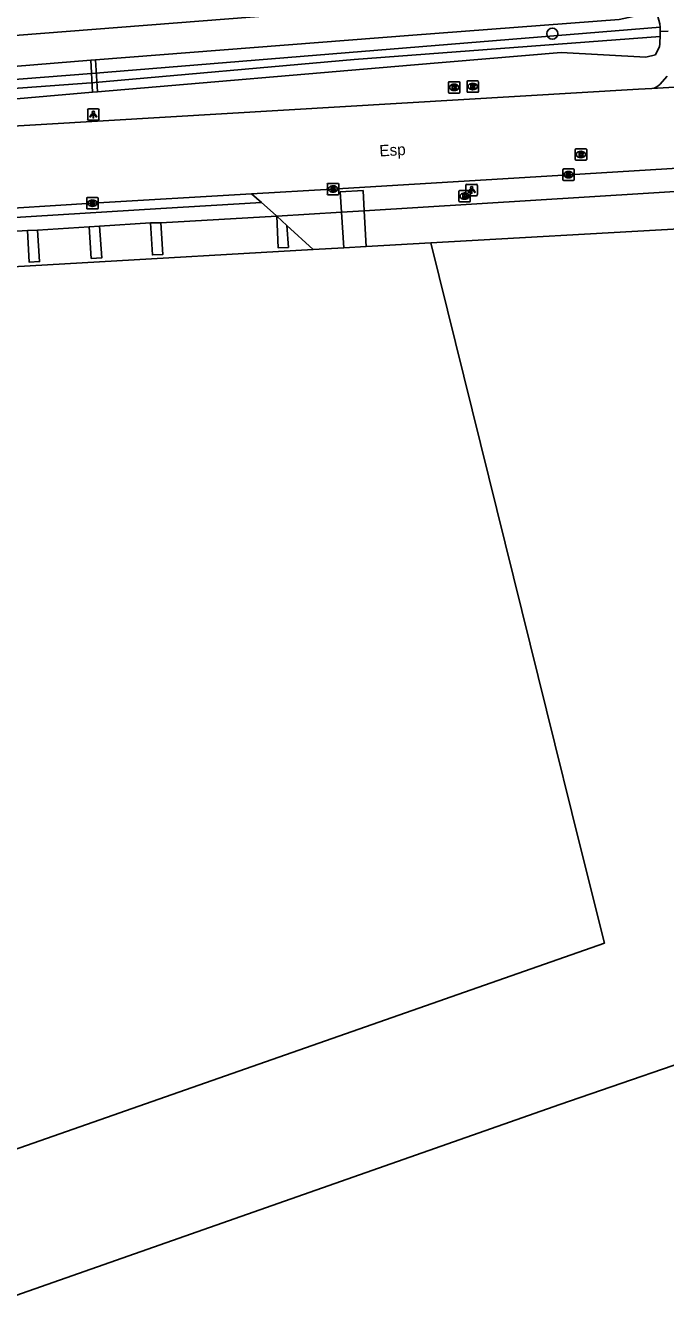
# Model space of a CAD drawing. Extents: x 161389 to 162585, y 388479 to 389761.
# Drawn here: x 162034.7 to 162090.8, y 388865.1 to 388977.1 of the extents above; entities that cross this region are included whole.
import ezdxf

# ---------------------------------------------------------------- set-up
doc = ezdxf.new("R2010")
doc.units = 0
for name, color, linetype in [('IMGEO_Berm_groen', 7, 'Continuous'), ('IMGEO_Boom', 7, 'Continuous'), ('IMGEO_Brandkraan', 7, 'Continuous'), ('IMGEO_Dek', 7, 'Continuous'), ('IMGEO_Grasland_overig', 7, 'Continuous'), ('IMGEO_Groenvoorziening', 7, 'Continuous'), ('IMGEO_Kolk', 7, 'Continuous'), ('IMGEO_Lichtpunt', 7, 'Continuous'), ('IMGEO_Openbare_ruimte_label', 7, 'Continuous'), ('IMGEO_Pand', 7, 'Continuous'), ('IMGEO_Rijbaan_lokaal_gesloten', 7, 'Continuous'), ('IMGEO_Rijbaan_lokaal_open', 7, 'Continuous'), ('IMGEO_Rioolput', 7, 'Continuous'), ('IMGEO_Voetpad_gesloten', 7, 'Continuous'), ('IMGEO_Voetpad_open', 7, 'Continuous'), ('IMGEO_Waterloop', 7, 'Continuous')]:
    doc.layers.add(name, color=color, linetype=linetype)

msp = doc.modelspace()

# ---------------------------------------------------------------- linework, layer by layer
at = {"layer": 'IMGEO_Berm_groen'}
for points in [[(162090.32, 388976.08), (162090.3, 388975.58), (162090.29, 388975.42), (162090.26, 388975.21), (162089.92, 388974.48), (162089.09, 388974.29), (162081.65, 388974.7), (162068.44, 388973.58), (162041, 388971.25), (162040.56, 388971.22), (161994.51, 388967.19), (161960.26, 388964.84), (161958.25, 388964.73)], [(162091.02, 388976.56), (162090.33, 388976.53)]]:
    msp.add_lwpolyline(points, dxfattribs=at)
at = {"layer": 'IMGEO_Boom'}
msp.add_circle((162080.88, 388976.34), 0.489, dxfattribs=at)
at = {"layer": 'IMGEO_Brandkraan'}
for p, q in [((162072.69, 388961.67), (162072.69, 388962.53)), ((162072.77, 388962.6), (162073.62, 388962.6)), ((162073.18, 388962.38), (162073.21, 388962.38)), ((162073.69, 388962.53), (162073.69, 388961.67)), ((162073.62, 388961.6), (162072.77, 388961.6)), ((162073.2, 388961.82), (162073.18, 388961.82))]:
    msp.add_line(p, q, dxfattribs=at)
for points in [[(162072.69, 388961.67), (162072.69, 388962.53)], [(162072.77, 388962.6), (162073.62, 388962.6)], [(162073.04, 388962.3), (162073.04, 388961.9), (162073.25, 388961.9)], [(162073.27, 388962.3), (162073.04, 388962.3)], [(162073.22, 388962.22), (162073.17, 388962.22), (162073.17, 388962.14)], [(162073.69, 388962.53), (162073.69, 388961.67)], [(162073.62, 388961.6), (162072.77, 388961.6)], [(162073.17, 388962.14), (162073.22, 388962.14)], [(162073.23, 388962.07), (162073.17, 388962.07), (162073.17, 388961.98)], [(162073.17, 388961.98), (162073.23, 388961.98)]]:
    msp.add_lwpolyline(points, dxfattribs=at)
for centre, radius, start, end in [((162072.77, 388962.52), 0.0765, 91.552, 178.448), ((162072.77, 388962.52), 0.0765, 91.552, 178.448), ((162073.22, 388962.18), 0.0379, 267.8285, 90.9355), ((162073.28, 388962.15), 0.145, 59.4692, 91.5367), ((162073.3, 388962.2), 0.0922, 285.5137, 58.1501), ((162073.62, 388962.52), 0.0765, 1.552, 88.448), ((162073.62, 388962.52), 0.0765, 1.552, 88.448), ((162072.77, 388961.67), 0.0765, 181.552, 268.448), ((162072.77, 388961.67), 0.0765, 181.552, 268.448), ((162073.23, 388962.03), 0.0404, 269.8759, 90.5077), ((162073.26, 388962.15), 0.251, 268.6676, 293.5347), ((162073.31, 388962.01), 0.105, 301.3115, 78.989), ((162073.62, 388961.67), 0.0765, 271.552, 358.448), ((162073.62, 388961.67), 0.0765, 271.552, 358.448)]:
    msp.add_arc(centre, radius, start, end, dxfattribs=at)
for centre, major_axis, ratio, start_param, end_param in [((162073.18, 388962.1), (-0.387, 0.002), 0.722429, 4.712389, 7.853982), ((162073.2, 388962.1), (-0.39, 0.002), 0.717154, 1.570796, 4.712389)]:
    msp.add_ellipse(centre, major_axis=major_axis, ratio=ratio, start_param=start_param, end_param=end_param, dxfattribs=at)
at = {"layer": 'IMGEO_Dek'}
msp.add_lwpolyline([(162040.84, 388974.05), (162040.43, 388974.02), (162040.56, 388971.22), (162041, 388971.25)], close=True, dxfattribs=at)
at = {"layer": 'IMGEO_Grasland_overig'}
msp.add_lwpolyline([(161937.26, 388968.67), (162000, 388973.56), (162090.78, 388980.64)], dxfattribs=at)
at = {"layer": 'IMGEO_Groenvoorziening'}
msp.add_lwpolyline([(162090.32, 388976.9), (162090.31, 388977.2), (162090.14, 388977.85), (162089.45, 388978.17), (162086.74, 388977.59), (162068.65, 388976.22), (162040.84, 388974.05), (162040.43, 388974.02), (162015.77, 388972.01), (161959.76, 388967.69), (161957.89, 388967.38), (161957.63, 388966.99), (161957.64, 388966.8)], dxfattribs=at)
at = {"layer": 'IMGEO_Kolk'}
for p, q in [((162081.8, 388963.55), (162081.8, 388964.4)), ((162081.87, 388964.48), (162082.73, 388964.48)), ((162082.8, 388964.4), (162082.8, 388963.55)), ((162082.73, 388963.48), (162081.87, 388963.48)), ((162082.29, 388964.26), (162082.31, 388964.26)), ((162082.31, 388963.7), (162082.29, 388963.7)), ((162061.16, 388962.29), (162061.16, 388963.15)), ((162061.23, 388963.22), (162062.08, 388963.22)), ((162062.08, 388962.22), (162061.23, 388962.22)), ((162061.64, 388963), (162061.67, 388963)), ((162061.67, 388962.44), (162061.64, 388962.44)), ((162062.16, 388963.15), (162062.16, 388962.29)), ((162040.07, 388961.05), (162040.07, 388961.9)), ((162040.14, 388961.98), (162040.99, 388961.98)), ((162040.58, 388961.2), (162040.55, 388961.2)), ((162040.56, 388961.76), (162040.58, 388961.76)), ((162041.07, 388961.9), (162041.07, 388961.05)), ((162040.99, 388960.98), (162040.14, 388960.98))]:
    msp.add_line(p, q, dxfattribs=at)
for points in [[(162081.8, 388963.55), (162081.8, 388964.4)], [(162081.87, 388964.48), (162082.73, 388964.48)], [(162082.8, 388964.4), (162082.8, 388963.55)], [(162082.73, 388963.48), (162081.87, 388963.48)], [(162082.12, 388964.18), (162082.24, 388964.18), (162082.24, 388964.03), (162082.37, 388964.18), (162082.54, 388964.18), (162082.39, 388964.03), (162082.54, 388963.78), (162082.39, 388963.78), (162082.31, 388963.94), (162082.24, 388963.87), (162082.24, 388963.78), (162082.12, 388963.78), (162082.12, 388964.18)], [(162061.16, 388962.29), (162061.16, 388963.15)], [(162061.23, 388963.22), (162062.08, 388963.22)], [(162062.08, 388962.22), (162061.23, 388962.22)], [(162061.48, 388962.92), (162061.6, 388962.92), (162061.6, 388962.77), (162061.73, 388962.92), (162061.89, 388962.92), (162061.75, 388962.77), (162061.9, 388962.52), (162061.75, 388962.52), (162061.66, 388962.68), (162061.6, 388962.62), (162061.6, 388962.52), (162061.48, 388962.52), (162061.48, 388962.92)], [(162062.16, 388963.15), (162062.16, 388962.29)], [(162040.07, 388961.05), (162040.07, 388961.9)], [(162040.14, 388961.98), (162040.99, 388961.98)], [(162040.39, 388961.68), (162040.51, 388961.68), (162040.51, 388961.53), (162040.64, 388961.68), (162040.81, 388961.68), (162040.66, 388961.53), (162040.81, 388961.28), (162040.66, 388961.28), (162040.58, 388961.44), (162040.51, 388961.38), (162040.51, 388961.28), (162040.39, 388961.28), (162040.39, 388961.68)], [(162041.07, 388961.9), (162041.07, 388961.05)], [(162040.99, 388960.98), (162040.14, 388960.98)]]:
    msp.add_lwpolyline(points, dxfattribs=at)
for centre, start, end in [((162081.88, 388964.4), 91.552, 178.448), ((162081.88, 388964.4), 91.552, 178.448), ((162082.72, 388964.4), 1.552, 88.448), ((162082.72, 388964.4), 1.552, 88.448), ((162081.88, 388963.55), 181.552, 268.448), ((162081.88, 388963.55), 181.552, 268.448), ((162082.72, 388963.55), 271.552, 358.448), ((162082.72, 388963.55), 271.552, 358.448), ((162061.23, 388963.14), 91.552, 178.448), ((162061.23, 388963.14), 91.552, 178.448), ((162061.23, 388962.3), 181.552, 268.448), ((162061.23, 388962.3), 181.552, 268.448), ((162062.08, 388963.14), 1.552, 88.448), ((162062.08, 388963.14), 1.552, 88.448), ((162062.08, 388962.3), 271.552, 358.448), ((162062.08, 388962.3), 271.552, 358.448), ((162040.14, 388961.9), 91.552, 178.448), ((162040.14, 388961.9), 91.552, 178.448), ((162040.14, 388961.05), 181.552, 268.448), ((162040.14, 388961.05), 181.552, 268.448), ((162040.99, 388961.9), 1.552, 88.448), ((162040.99, 388961.9), 1.552, 88.448), ((162040.99, 388961.05), 271.552, 358.448), ((162040.99, 388961.05), 271.552, 358.448)]:
    msp.add_arc(centre, 0.0765, start, end, dxfattribs=at)
for centre, major_axis, ratio, start_param, end_param in [((162082.29, 388963.98), (-0.387, 0.002), 0.722429, 4.712389, 7.853982), ((162082.31, 388963.98), (-0.39, 0.002), 0.717154, 1.570796, 4.712389), ((162061.64, 388962.72), (-0.387, 0.002), 0.722429, 4.712389, 7.853982), ((162061.67, 388962.72), (-0.39, 0.002), 0.717154, 1.570796, 4.712389), ((162040.55, 388961.48), (-0.387, 0.002), 0.722429, 4.712389, 7.853982), ((162040.58, 388961.48), (-0.39, 0.002), 0.717154, 1.570796, 4.712389)]:
    msp.add_ellipse(centre, major_axis=major_axis, ratio=ratio, start_param=start_param, end_param=end_param, dxfattribs=at)
at = {"layer": 'IMGEO_Lichtpunt'}
for p, q in [((162040.15, 388969.65), (162040.15, 388968.85)), ((162040.15, 388969.65), (162040.15, 388968.85)), ((162041.05, 388969.75), (162040.24, 388969.75)), ((162041.05, 388969.75), (162040.24, 388969.75)), ((162041.14, 388968.85), (162041.14, 388969.65)), ((162041.14, 388968.85), (162041.14, 388969.65)), ((162040.24, 388968.75), (162041.05, 388968.75)), ((162040.24, 388968.75), (162041.05, 388968.75)), ((162073.31, 388963.04), (162073.31, 388962.23)), ((162073.31, 388963.04), (162073.31, 388962.23)), ((162074.21, 388963.13), (162073.4, 388963.13)), ((162074.21, 388963.13), (162073.4, 388963.13)), ((162074.31, 388962.23), (162074.31, 388963.04)), ((162074.31, 388962.23), (162074.31, 388963.04)), ((162073.4, 388962.13), (162074.21, 388962.13)), ((162073.4, 388962.13), (162074.21, 388962.13))]:
    msp.add_line(p, q, dxfattribs=at)
for points in [[(162040.52, 388969.32), (162040.56, 388969.29), (162040.37, 388969.03), (162040.33, 388969.05), (162040.52, 388969.32)], [(162040.62, 388969.27), (162040.67, 388969.27), (162040.67, 388968.95), (162040.62, 388968.95), (162040.62, 388969.27)], [(162040.73, 388969.29), (162040.77, 388969.32), (162040.96, 388969.05), (162040.92, 388969.03), (162040.73, 388969.29)], [(162073.68, 388962.7), (162073.72, 388962.67), (162073.54, 388962.41), (162073.5, 388962.44), (162073.68, 388962.7)], [(162073.79, 388962.65), (162073.83, 388962.65), (162073.83, 388962.33), (162073.79, 388962.33), (162073.79, 388962.65)], [(162073.9, 388962.67), (162073.93, 388962.7), (162074.12, 388962.44), (162074.08, 388962.41), (162073.9, 388962.67)]]:
    msp.add_lwpolyline(points, dxfattribs=at)
for centre in [(162040.65, 388969.45), (162073.81, 388962.83)]:
    msp.add_circle(centre, 0.0994, dxfattribs=at)
for centre, start, end in [((162040.24, 388969.65), 90, 180), ((162040.24, 388969.65), 90, 180), ((162041.05, 388969.65), 0, 90), ((162041.05, 388969.65), 0, 90), ((162040.24, 388968.85), 180, 270), ((162040.24, 388968.85), 180, 270), ((162041.05, 388968.85), 270, 0), ((162041.05, 388968.85), 270, 360), ((162073.4, 388963.04), 90, 180), ((162073.4, 388963.04), 90, 180), ((162073.4, 388962.23), 180, 270), ((162073.4, 388962.23), 180, 270), ((162074.21, 388963.04), 0, 90), ((162074.21, 388963.04), 0, 90), ((162074.21, 388962.23), 270, 0), ((162074.21, 388962.23), 270, 360)]:
    msp.add_arc(centre, 0.0946, start, end, dxfattribs=at)
at = {"layer": 'IMGEO_Pand'}
for points in [[(162028.92, 388876.85), (162085.44, 388896.62), (162083.85, 388903.02), (162082.6, 388908.07), (162081.11, 388914.09), (162070.24, 388958)], [(162064.56, 388957.68), (162062.59, 388957.56)], [(162070.24, 388958), (162064.56, 388957.68)], [(162059.92, 388957.41), (161978.9, 388952.75)], [(162062.59, 388957.56), (162059.92, 388957.41)], [(162103.73, 388829.7), (162094.5, 388851.66), (162092.94, 388855.37), (162107.79, 388861.6), (162096.81, 388887.73), (162081.55, 388882.48), (162023.42, 388862.08), (162022.89, 388863.24), (162023.26, 388863.4), (162023.09, 388863.77), (162015.75, 388860.39)]]:
    msp.add_lwpolyline(points, dxfattribs=at)
at = {"layer": 'IMGEO_Rijbaan_lokaal_gesloten'}
for points in [[(162104.97, 388972.44), (162089.61, 388971.53)], [(161975.68, 388964.77), (162000, 388966.23), (162088.43, 388971.46), (162089.61, 388971.53)], [(162054.5, 388962.3), (162061.55, 388962.72), (162082.34, 388963.98), (162095.22, 388964.74)], [(162054.5, 388962.3), (162040.57, 388961.48), (162020.15, 388960.21), (162000, 388959), (161979.08, 388957.75), (161976.66, 388957.62)]]:
    msp.add_lwpolyline(points, dxfattribs=at)
at = {"layer": 'IMGEO_Rijbaan_lokaal_open'}
msp.add_lwpolyline([(162090.3, 388971.89), (162090.96, 388972.62)], dxfattribs=at)
msp.add_arc((162089.52, 388972.55), 1.02, 275.2914, 319.8199, dxfattribs=at)
at = {"layer": 'IMGEO_Rioolput'}
for p, q in [((162071.78, 388971.2), (162071.78, 388972.05)), ((162071.85, 388972.13), (162072.7, 388972.13)), ((162072.7, 388971.13), (162071.85, 388971.13)), ((162072.29, 388971.35), (162072.26, 388971.35)), ((162072.27, 388971.91), (162072.29, 388971.91)), ((162072.78, 388972.05), (162072.78, 388971.2)), ((162073.41, 388971.28), (162073.41, 388972.13)), ((162073.48, 388972.21), (162074.33, 388972.21)), ((162074.33, 388971.21), (162073.48, 388971.21)), ((162073.92, 388971.43), (162073.89, 388971.43)), ((162073.9, 388971.99), (162073.92, 388971.99)), ((162074.41, 388972.13), (162074.41, 388971.28)), ((162082.89, 388965.32), (162082.89, 388966.18)), ((162082.96, 388966.25), (162083.81, 388966.25)), ((162083.37, 388966.03), (162083.4, 388966.03)), ((162083.89, 388966.18), (162083.89, 388965.32)), ((162083.81, 388965.25), (162082.96, 388965.25)), ((162083.4, 388965.47), (162083.37, 388965.47))]:
    msp.add_line(p, q, dxfattribs=at)
for points in [[(162071.78, 388971.2), (162071.78, 388972.05)], [(162071.85, 388972.13), (162072.7, 388972.13)], [(162072.7, 388971.13), (162071.85, 388971.13)], [(162072.37, 388971.83), (162072.11, 388971.83), (162072.11, 388971.43)], [(162072.11, 388971.43), (162072.24, 388971.43), (162072.24, 388971.59), (162072.25, 388971.59)], [(162072.29, 388971.75), (162072.24, 388971.75), (162072.24, 388971.67)], [(162072.24, 388971.67), (162072.29, 388971.67)], [(162072.3, 388971.56), (162072.37, 388971.43), (162072.51, 388971.43), (162072.44, 388971.55)], [(162072.78, 388972.05), (162072.78, 388971.2)], [(162073.41, 388971.28), (162073.41, 388972.13)], [(162073.48, 388972.21), (162074.33, 388972.21)], [(162074.33, 388971.21), (162073.48, 388971.21)], [(162074, 388971.9), (162073.74, 388971.91), (162073.74, 388971.51)], [(162073.74, 388971.51), (162073.87, 388971.51), (162073.87, 388971.67), (162073.88, 388971.67)], [(162073.92, 388971.83), (162073.87, 388971.83), (162073.87, 388971.74)], [(162073.87, 388971.74), (162073.92, 388971.74)], [(162073.93, 388971.64), (162074, 388971.51), (162074.14, 388971.51), (162074.07, 388971.63)], [(162074.41, 388972.13), (162074.41, 388971.28)], [(162082.89, 388965.32), (162082.89, 388966.18)], [(162082.96, 388966.25), (162083.81, 388966.25)], [(162083.47, 388965.95), (162083.22, 388965.95), (162083.22, 388965.55)], [(162083.22, 388965.55), (162083.35, 388965.55), (162083.35, 388965.71), (162083.36, 388965.71)], [(162083.4, 388965.87), (162083.35, 388965.87), (162083.35, 388965.79)], [(162083.35, 388965.79), (162083.4, 388965.79)], [(162083.4, 388965.68), (162083.48, 388965.55), (162083.61, 388965.55), (162083.55, 388965.68)], [(162083.89, 388966.18), (162083.89, 388965.32)], [(162083.81, 388965.25), (162082.96, 388965.25)]]:
    msp.add_lwpolyline(points, dxfattribs=at)
for centre, radius, start, end in [((162071.85, 388972.05), 0.0765, 91.552, 178.448), ((162071.85, 388972.05), 0.0765, 91.552, 178.448), ((162071.85, 388971.2), 0.0765, 181.552, 268.448), ((162071.85, 388971.2), 0.0765, 181.552, 268.448), ((162072.25, 388971.54), 0.0533, 26.0293, 88.6989), ((162072.3, 388971.65), 0.0964, 77.0061, 93.1865), ((162072.27, 388971.86), 0.19, 274.7715, 282.9687), ((162072.31, 388971.71), 0.0378, 276.6634, 79.6772), ((162072.37, 388971.72), 0.109, 350.3612, 89.416), ((162072.36, 388971.72), 0.112, 277.5842, 350.9817), ((162072.35, 388971.5), 0.108, 29.5134, 73.7905), ((162072.7, 388972.05), 0.0765, 1.552, 88.448), ((162072.7, 388972.05), 0.0765, 1.552, 88.448), ((162072.7, 388971.2), 0.0765, 271.552, 358.448), ((162072.7, 388971.2), 0.0765, 271.552, 358.448), ((162073.48, 388972.13), 0.0765, 91.552, 178.448), ((162073.48, 388972.13), 0.0765, 91.552, 178.448), ((162073.48, 388971.28), 0.0765, 181.552, 268.448), ((162073.48, 388971.28), 0.0765, 181.552, 268.448), ((162073.88, 388971.62), 0.0533, 26.0293, 88.6989), ((162073.93, 388971.73), 0.0964, 77.0061, 93.1865), ((162073.9, 388971.93), 0.19, 274.7715, 282.9687), ((162073.94, 388971.79), 0.0378, 276.6634, 79.6772), ((162074, 388971.79), 0.109, 350.3612, 89.416), ((162073.99, 388971.79), 0.112, 277.5842, 350.9817), ((162073.98, 388971.58), 0.108, 29.5134, 73.7905), ((162074.33, 388972.13), 0.0765, 1.552, 88.448), ((162074.33, 388972.13), 0.0765, 1.552, 88.448), ((162074.33, 388971.28), 0.0765, 271.552, 358.448), ((162074.33, 388971.28), 0.0765, 271.552, 358.448), ((162082.96, 388966.17), 0.0765, 91.552, 178.448), ((162082.96, 388966.17), 0.0765, 91.552, 178.448), ((162083.36, 388965.66), 0.0533, 26.0293, 88.6989), ((162083.41, 388965.77), 0.0964, 77.0061, 93.1865), ((162083.38, 388965.98), 0.19, 274.7715, 282.9687), ((162083.42, 388965.83), 0.0378, 276.6634, 79.6772), ((162083.47, 388965.84), 0.109, 350.3612, 89.416), ((162083.47, 388965.84), 0.112, 277.5842, 350.9817), ((162083.46, 388965.62), 0.108, 29.5134, 73.7905), ((162083.81, 388966.17), 0.0765, 1.552, 88.448), ((162083.81, 388966.17), 0.0765, 1.552, 88.448), ((162082.96, 388965.33), 0.0765, 181.552, 268.448), ((162082.96, 388965.33), 0.0765, 181.552, 268.448), ((162083.81, 388965.33), 0.0765, 271.552, 358.448), ((162083.81, 388965.33), 0.0765, 271.552, 358.448)]:
    msp.add_arc(centre, radius, start, end, dxfattribs=at)
for centre, major_axis, ratio, start_param, end_param in [((162072.26, 388971.63), (-0.387, 0.002), 0.722429, 4.712389, 7.853982), ((162072.29, 388971.63), (-0.39, 0.002), 0.717154, 1.570796, 4.712389), ((162073.89, 388971.71), (-0.387, 0.002), 0.722429, 4.712389, 7.853982), ((162073.92, 388971.71), (-0.39, 0.002), 0.717154, 1.570796, 4.712389), ((162083.37, 388965.75), (-0.387, 0.002), 0.722429, 4.712389, 7.853982), ((162083.4, 388965.75), (-0.39, 0.002), 0.717154, 1.570796, 4.712389)]:
    msp.add_ellipse(centre, major_axis=major_axis, ratio=ratio, start_param=start_param, end_param=end_param, dxfattribs=at)
at = {"layer": 'IMGEO_Voetpad_gesloten'}
for points in [[(162040.43, 388974.02), (162040.56, 388971.22), (162041, 388971.25), (162040.84, 388974.05), (162040.43, 388974.02)], [(162064.39, 388960.81), (162064.29, 388962.58), (162062.29, 388962.47), (162062.4, 388960.69)], [(162062.4, 388960.69), (162064.39, 388960.81)], [(162062.4, 388960.69), (162062.59, 388957.56)], [(162064.56, 388957.68), (162064.39, 388960.81)]]:
    msp.add_lwpolyline(points, dxfattribs=at)
at = {"layer": 'IMGEO_Voetpad_open'}
for points in [[(162055.38, 388961.54), (162054.5, 388962.3)], [(162064.39, 388960.81), (162094.01, 388962.66)], [(161976.29, 388956.8), (162000, 388958.19), (162023.81, 388959.61), (162046.55, 388961.01), (162055.38, 388961.54)], [(162055.38, 388961.54), (162056.66, 388960.41), (162056.74, 388960.33)], [(162056.74, 388960.33), (162046.57, 388959.77)], [(162056.74, 388960.33), (162062.4, 388960.69)], [(162057.62, 388959.53), (162057.74, 388957.61), (162056.84, 388957.57), (162056.74, 388960.33)], [(162056.74, 388960.33), (162057.62, 388959.53)], [(162034.88, 388959.09), (162024.99, 388958.47)], [(162035.75, 388959.12), (162035.93, 388956.36), (162035.01, 388956.32), (162034.88, 388959.09)], [(162035.75, 388959.12), (162034.88, 388959.09)], [(162040.28, 388959.41), (162035.75, 388959.12)], [(162041.19, 388959.46), (162041.38, 388956.68), (162040.47, 388956.64), (162040.28, 388959.41)], [(162041.19, 388959.46), (162040.28, 388959.41)], [(162045.67, 388959.76), (162041.19, 388959.46)], [(162046.57, 388959.77), (162046.74, 388956.99), (162045.82, 388956.95), (162045.67, 388959.76)], [(162046.57, 388959.77), (162045.67, 388959.76)], [(162059.92, 388957.41), (162057.62, 388959.53)], [(162070.24, 388958), (162092.01, 388959.23)]]:
    msp.add_lwpolyline(points, dxfattribs=at)
at = {"layer": 'IMGEO_Waterloop'}
for points in [[(162090.32, 388976.9), (162040.48, 388972.84), (161957.68, 388966.38)], [(162090.33, 388976.53), (162090.32, 388976.9)], [(161957.72, 388965.87), (161976.82, 388967.38), (162010.89, 388969.87), (162040.46, 388972.02), (162063.52, 388974.08), (162090.32, 388976.08)], [(162090.33, 388976.53), (162090.32, 388976.08)]]:
    msp.add_lwpolyline(points, dxfattribs=at)

# ---------------------------------------------------------------- texts
at = {"layer": 'IMGEO_Openbare_ruimte_label'}
msp.add_text('Esp', height=1, rotation=3.4405, dxfattribs=at).set_placement((162065.75, 388965.57))

doc.saveas('drawing.dxf')
